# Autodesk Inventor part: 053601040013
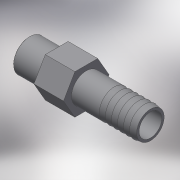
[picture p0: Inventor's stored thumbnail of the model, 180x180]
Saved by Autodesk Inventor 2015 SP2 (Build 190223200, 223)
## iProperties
Created: 2017-10
Part Number: 053601040013
Material: Generic
Description: PLASSON THREADED HOSE NOZZLE 1.1/4"-40
Document SubType Name: Modeling
Designer: KIM
Density: 1 g/cm^3
Appearance: Default
Author: KIM
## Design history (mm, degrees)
derived "053601.ipt"
feature "Solid1::053601.ipt"
tag "TaggingFeature1"
body "Solid1"
other parameters: "d0" = 91, "d1" = 170 deg, "d6" = 29.337, "d8" = 27.3, "d9" = 41.91, "d10" = 46, "d11" = 22, "d12" = 16, "d13" = 16, "d14" = 0, "d15" = 0.12, "d_" = 12, "H_" = 91, "R_" = 41.91, "C_" = 46, "B_" = 16, "Lt_" = 22
